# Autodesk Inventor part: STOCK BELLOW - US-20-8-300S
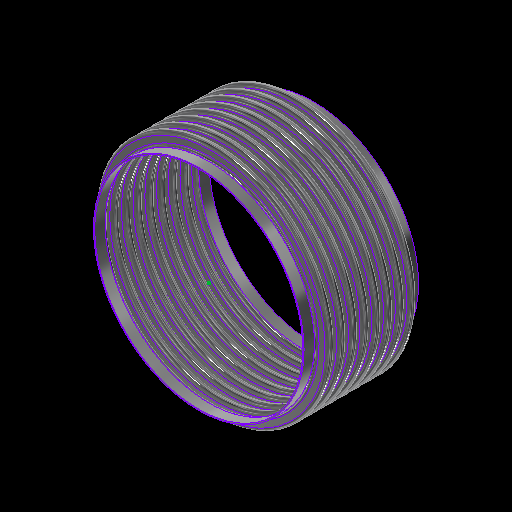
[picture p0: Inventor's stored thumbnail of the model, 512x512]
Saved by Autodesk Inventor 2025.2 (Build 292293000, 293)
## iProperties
Category: 16 GA (0.060 THICK)
RuleStatus: InUse
Created: 2024-01
Part Number: STOCK BELLOW - US-20-8-300S
Project: =STOCK BELLOWS: <Stock Number><SFILL>
Material: ASTM A240-304
Description: =STOCK BELLOWS: <Stock Number>, <SID_> I.D., <SOD_> O.D., <SPLY_> PLY, <Category>, <SNET_CONS> CONS.<PITCH_><STANGENT_> TANGENT<SFILL>
Document SubType Name: Sheet Metal
Designer: GS
Stock Number: U.S-20-8-300S
Surface Area: 21924.1 cm^2
Volume: 3296.49 cm^3
Sheet Metal Rule: Default
Appearance: STAINLESS STEEL
Mass: 26560.8 g
Density: 8.05729 g/cm^3
THK: 0.036
ID: 3.500
OD: 4.250
CONS_: 2
PITCH: 0.500
TANGENT: 0.500
BELLOWS_UPSET: 0.000
d79: 1.000
d82: 1.000
d83: 26.000
d84: 24.000
d174: 8
d214: 8
STHK_: 0.060
SID_: 20.000
SOD_: 22.500
SPITCH_: 1.125
STANGENT__: 1.000
SBELLOWS_UPSET_: 0.000
SDIFF_TAN: 1.000
d252: 2
d275: 2
d287: 0.050
d289: 0.500
d290: 0.000
SOD_NECK: 20 1/4
PLY: 1
PSET: 4.178
PBAR: 1.035
COUNTER: 1.500
NET_TUBE: 3.071
CONS: 2
S_CONS: 0
NET_CONS: 2
ID_M: 88.90 mm
OD_M: 107.95 mm
THK_M: 0.91 mm
ID_U: 3.500 in
OD_U: 4.250 in
THK_U: 0.036 in
TANGENT2: 0.500
TAN_TO_TAN: 1.000 in
d80: 2.571
d81: 10
SID: 2.375
SCONS_: 8
SPITCH: 0.250
STANGENT_: 1.000
SBELLOWS_UPSET: 0.000
SNET_CONS: 8
SS_CONS: 0
SCONS: 8
d190: 8
d191: 1
d192: 1
d193: 8
d194: 0
SIZE: 20.00
PRESSURE: 300
d230: 8
STANGENT: 4.000
SPLY_: 2
d233: 8
d234: 0
d263: 2
d265: 1
d268: 2
d269: 0
d286: 2
d288: 1
d291: 2
d292: 0
SREROLL: 0.750
BLETP: 0.000 ul
PRES_Copy: 85
MATTABLE: 20 GA (0.036 THICK)
PART_NUMBER: U.S-20-8-300S
PITCH_: =, <SPITCH_> PITCH,
CFILL: .
SFILL: .
MESH: ,
COMP: 1.51
EXT: 0.76
LAT: 0.21
ANG: 458
ASR: 11839
LSR: 99004
ANSR: 11664
PRES: 300
COMPM: 15.1
EXTM: 7.55
LATM: 2.10
ASRM: 2073.364
PRESM: 20.684
LSRM: 17338.571
ANSRM: 2042.716
TEMPMIN: 20
TEMPMAX: 800
TEMPMINM: -7
TEMPMAXM: 427
WEIGHTM: 26.561
WEIGHT: 58.556
Author: GS
Keywords: 20 GA (0.036 THICK)
Comments: =STOCK BELLOW - <STOCK NUMBER>
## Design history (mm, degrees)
sketch "Sketch2"
  geometry: L1 (0, -177.245)-(0, 562.856) reference; L2 (45.364, 0)-(44.45, 0); L3 (48.082, -2.718)-(50.343, -2.718); L4 (48.082, -3.632)-(50.343, -3.632); L5 (50.343, -9.982)-(48.082, -9.982); L6 (50.343, -9.068)-(48.082, -9.068); L7 (45.364, -12.7)-(44.45, -12.7); L8 (48.082, 0)-(48.082, -12.7); L9 (50.343, -6.35)-(53.975, -6.35); L10 (44.45, 0)-(44.45, -12.7); L11 (20.376, 102.841)-(20.376, 101.926); L12 (58.262, 457.127)-(58.262, 349.177); L13 (58.262, 444.427)-(58.262, 336.477); L14 (93.133, -58.817)-(93.133, -71.517); L15 (118.746, -66.401)-(118.746, -66.401); L16 (50.343, -9.068)-(50.343, -9.982); L17 (48.082, -9.068)-(48.082, -9.982); L18 (48.082, -9.525)-(50.343, -9.525); L19 (53.975, 0)-(53.975, -12.7); L20 (-50.343, -9.068)-(-50.343, -9.982); L21 (-50.343, -2.718)-(-48.082, -2.718); L22 (-50.343, -3.632)-(-48.082, -3.632); L23 (-48.082, -9.068)-(-50.343, -9.068); L24 (-50.343, -9.525)-(-48.082, -9.525); L25 (-48.082, -9.982)-(-50.343, -9.982); L26 (-48.082, -9.068)-(-48.082, -9.982); L27 (-44.45, 0.653)-(-44.45, -12.047); L28 (-48.082, -6.35)-(-44.45, -6.35); L29 (-50.343, 0.653)-(-50.343, -12.7); L30 (-53.061, 0)-(-53.975, 0); L31 (-53.975, 0)-(-53.975, -12.7); L32 (-53.061, -12.7)-(-53.975, -12.7); A1 r 2.718 centre (48.082, 0) between (45.364, 0) and (48.082, -2.718); A2 r 3.632 centre (48.082, 0) between (44.45, 0) and (48.082, -3.632); A3 r 3.632 centre (50.343, -6.35) between (50.343, -9.982) and (50.343, -2.718); A4 r 2.718 centre (50.343, -6.35) between (50.343, -9.068) and (50.343, -3.632); A5 r 2.718 centre (48.082, -12.7) between (48.082, -9.982) and (45.364, -12.7); A6 r 3.632 centre (48.082, -12.7) between (48.082, -9.068) and (44.45, -12.7); A7 r 3.175 centre (50.343, -6.35) between (50.343, -9.525) and (53.518, -6.35); A8 r 3.175 centre (48.082, -12.7) between (48.082, -9.525) and (44.907, -12.7); A9 r 2.718 centre (-50.343, -12.7) between (-50.343, -9.982) and (-53.061, -12.7); A10 r 2.718 centre (-48.082, -6.35) between (-48.082, -9.068) and (-48.082, -3.632); A11 r 3.175 centre (-48.082, -6.35) between (-48.082, -9.525) and (-44.907, -6.35); A12 r 3.632 centre (-48.082, -6.35) between (-48.082, -9.982) and (-48.082, -2.718); A13 r 3.175 centre (-50.343, -12.7) between (-50.343, -9.525) and (-53.518, -12.7); A14 r 3.632 centre (-50.343, -12.7) between (-50.343, -9.068) and (-53.975, -12.7); A15 r 2.718 centre (-50.343, 0) between (-53.061, 0) and (-50.343, -2.718); A16 r 3.632 centre (-50.343, 0) between (-53.975, 0) and (-50.343, -3.632); 10 further points
  constraints: 62 end point, 38 point on circle, 20 tangent, 16 centre point, 12 parallel, 9 midpoint, 7 vertical, 6 coincident, 6 concentric, 6 point on line, 4 equal radius, 4 perpendicular, 3 horizontal, 1 collinear, 1 horizontal alignment, 10 other
  dimensions: "THK" = 0.9144 distance of L11.start L11.end; "ID" = 88.9 distance of L11.end point (20.376, 13.026); "OD" = 107.95 distance of L12.start L12.end; "PITCH" = 12.7 distance of L12.start L13.start; "TANGENT" = 12.7 distance of L14.start L14.end; "BELLOWS_UPSET" = 0 distance of L15.start L15.end; "d43" = 88.9 diameter of L10 L1 (= ID); "d44" = 107.95 diameter of L9.end L1 (= OD); "d45" = 0.9144 distance between parallel lines of L5 L6 (computed from THK, PLY); "d46" = 3.6322 radius of A3 (computed from PITCH, THK, PLY); "UPSET_PITCH" = 12.7 distance of L2.end L7.end (derived); "SIDEWALL_ANGLE" = 360 deg dimension on L3 L9 (derived); "CON_GAP" = 5.4356 distance of point (48.082, -9.068) point (48.082, -3.632) (derived); "TAN1" = 4.98728 dimension on A8 (derived); "TAN2" = 4.98728 dimension on A7 (derived); "LEG1" = 2.2606 distance of L18.start L18.end (derived); "d278" = 0.9144 distance between parallel lines of L25 L23 (derived); "d279" = 3.6322 radius of A12 (derived); "d280" = 12.7 distance of L30.end L31.end (derived); "d281" = 360 deg dimension on L21 L28 (derived); "d282" = 5.4356 distance of point (-50.343, -9.068) point (-50.343, -3.632) (derived); "d283" = 4.98728 dimension on A13 (derived); "d284" = 4.98728 dimension on A11 (derived); "d285" = 2.2606 distance of L24.start L24.end (derived); "d293" = 88.9 diameter of L27 L1 (derived); "d294" = 107.95 diameter of L31 L1 (derived)
  node "Sketch Rectangular Pattern1" dims "d31" = 25.4, "ID" = 88.9
  node "Sketch Rectangular Pattern2" dims "d39" = 25.4, "PITCH" = 12.7
revolve "CONS" stored, may be unused: angle "d48" = 90 deg
node "BELLOW MIDPLANE"
pattern_linear "Rectangular Pattern2" dims "d52" = 12.7 (= UPSET_PITCH)
sketch "Sketch5"
  geometry: C1 r 45.364 at (0, 0) reference; C2 r 44.45 at (0, 0) reference
extrude "TANGENT" new body sketch "Sketch5" distance "d53" = 12.7 (= TANGENT); taper "d54" = 0 deg
revolve "SAMETAN" stored, may be unused: angle "d65" = 90 deg
revolve "DIFFTAN" stored, may be unused: angle "d70" = 90 deg
sketch "Sketch9"
  geometry: L1 (53.319, 0)-(-53.319, 0) reference; L2 (0, -17.78)-(0, 17.78) reference; L3 (38.085, 0)-(-38.085, 0); L4 (38.085, -11.906)-(38.085, 11.906); L5 (25.385, -11.906)-(25.385, 11.906); L6 (13.15, 11.906)-(13.15, -11.906); L7 (-25.385, -11.906)-(-25.385, 11.906); L8 (-38.085, -11.906)-(-38.085, 11.906); L9 (37.291, -11.906)-(37.291, 11.906); L10 (38.085, -11.906)-(37.291, -11.906); L11 (38.085, 11.906)-(37.291, 11.906); L12 (13.546, 11.906)-(12.753, 11.906); L13 (12.753, 11.906)-(12.753, -11.906); L14 (12.753, -11.906)-(13.546, -11.906); L15 (13.546, -11.906)-(13.546, 11.906); L16 (-13.546, 11.906)-(-13.546, -11.906); L17 (-13.15, 11.906)-(-13.15, -11.906); L18 (-13.546, -11.906)-(-12.753, -11.906); L19 (-12.753, -11.906)-(-12.753, 11.906); L20 (-12.753, 11.906)-(-13.546, 11.906); L21 (-38.085, -11.906)-(-37.291, -11.906); L22 (-37.291, -11.906)-(-37.291, 11.906); L23 (-37.291, 11.906)-(-38.085, 11.906); L24 (-38.085, 11.906)-(-38.085, -11.906); L25 (38.085, -0.397)-(-38.085, -0.397); L26 (-38.085, -0.397)-(-38.085, 0.397); L27 (-38.085, 0.397)-(38.085, 0.397); L28 (38.085, 0.397)-(38.085, -0.397); L29 (-38.085, 11.906)-(38.085, 11.906); L30 (38.085, 11.906)-(38.085, 12.7); L31 (38.085, 12.7)-(-38.085, 12.7); L32 (-38.085, 12.7)-(-38.085, 11.906); L33 (38.085, -11.906)-(-38.085, -11.906); L34 (-38.085, -11.906)-(-38.085, -12.7); L35 (-38.085, -12.7)-(38.085, -12.7); L36 (38.085, -12.7)-(38.085, -11.906); 30 further points
  constraints: 68 end point, 13 midpoint, 13 parallel, 8 horizontal, 7 perpendicular, 6 equal length, 3 point on line, 2 vertical, 14 other
  dimensions: "d115" = 23.8125 distance of L4.start L4.end (derived); "d116" = 12.7 distance between parallel lines of L4 L5 (derived); "d117" = 12.23516 distance between parallel lines of L5 L6 (derived); "d125" = 38.53427 distance between parallel lines of L7 L6 (derived); "d127" = 12.7 distance between parallel lines of L8 L7 (derived); "d128" = 24.93516 distance between parallel lines of L6 L4 (derived); "d130" = 76.16943 distance between parallel lines of L8 L4 (derived); "RULER_THK" = 0.79375 distance between parallel lines of L4 L9; "d135" = 0.79375 distance of L13.end L14.end (derived); "d138" = 26.29911 distance of L13.end L16.end (derived); "d143" = 0.79375 distance of L22.end L8.end (derived); "d144" = 0.79375 distance between parallel lines of L27 L25 (derived)
extrude "RULER" join sketch "Sketch9" distance "d149" = 0.79375 (derived); taper "d150" = 0 deg
extrude "BARS" join sketch "Sketch9" distance "d151" = 0.79375 (derived); taper "d152" = 0 deg
pattern_linear "Rectangular Pattern4" dims "d155" = 26.29911 (derived)
sketch "Sketch13"
  geometry: L1 (93.149, -52.467)-(93.149, -77.867); L2 (257.048, 0)-(254, 0); L3 (257.048, -28.575)-(254, -28.575); L4 (277.082, -22.955)-(262.668, -22.955); L5 (277.082, -19.907)-(262.668, -19.907); L6 (277.082, -14.287)-(285.75, -14.287); L7 (262.668, -5.62)-(277.082, -5.62); L8 (262.668, 0)-(262.668, -28.575); L9 (254, 0)-(254, -28.575); L10 (58.254, 75.069)-(58.254, -496.431); L11 (58.254, 46.494)-(58.254, -525.006); L12 (58.254, -10.656)-(58.254, -582.156); L13 (58.254, -39.231)-(58.254, -610.731); L14 (58.254, -67.806)-(58.254, -639.306); L15 (58.254, -96.381)-(58.254, -667.881); L16 (58.254, -124.956)-(58.254, -696.456); L17 (58.254, 17.919)-(58.254, -553.581); L18 (20.376, 103.45)-(20.376, 101.926); L19 (262.668, -8.668)-(277.082, -8.668); L20 (0, -856.437)-(0, 263.431) reference; L21 (-57.15, 0)-(342.9, 0) reference; A1 r 5.62 centre (262.668, 0) between (257.048, 0) and (262.668, -5.62); A2 r 5.62 centre (262.668, -28.575) between (262.668, -22.955) and (257.048, -28.575); A3 r 8.668 centre (262.668, -28.575) between (262.668, -19.907) and (254, -28.575); A4 r 5.62 centre (277.082, -14.287) between (277.082, -19.907) and (277.082, -8.668); A5 r 8.668 centre (277.082, -14.287) between (277.082, -22.955) and (277.082, -5.62); A6 r 8.668 centre (262.668, 0) between (254, 0) and (262.668, -8.668); 6 further points; 1 other entity
  constraints: 38 end point, 15 point on circle, 9 tangent, 6 centre point, 6 parallel, 5 vertical alignment, 4 point on line, 4 vertical, 3 coincident, 3 concentric, 2 collinear, 2 equal radius, 1 horizontal, 1 perpendicular, 23 other
  dimensions: "SBELLOWS_UPSET_" = 0 distance of point (118.762, -66.401) point (118.762, -66.401); "STOTAL_THK_BELLOW__" = 3.048 distance between parallel lines of L4 L5 (derived); "d224" = 8.66775 radius of A5 (derived); "d225" = 28.575 distance of L2.end L3.end (derived); "SSIDEWALL_ANGLE_" = 360 deg dimension on L7 L6 (derived); "SSCON_GAP_" = 11.2395 distance of point (262.668, -19.907) point (262.668, -8.668) (derived); "d235" = 508 diameter of L9 L20 (derived); "d236" = 571.5 diameter of L6.end L20 (derived)
  node "Sketch Rectangular Pattern4" dims "d228" = 25.4
  node "Sketch Rectangular Pattern5" dims "d229" = 25.4
revolve "SBELLOW" stored, may be unused: angle "d197" = 90 deg
pattern_linear "Rectangular Pattern5" dims "d204" = 28.575 (derived)
revolve "STANGENT" stored, may be unused: angle "d240" = 90 deg
revolve "SSAMETAN" stored, may be unused: angle "d241" = 90 deg
revolve "SDIFFTAN" stored, may be unused: angle "d246" = 90 deg
revolve "INVCON" stored, may be unused: angle "d295" = 90 deg
pattern_linear "Rectangular Pattern6" dims "d298" = 12.7 (derived)
revolve "INVTANGENT" stored, may be unused: angle "d302" = 90 deg
revolve "INVSAMETAN" stored, may be unused: angle "d307" = 90 deg
revolve "INVDIFFTAN" stored, may be unused: angle "d312" = 90 deg
sketch "ID BELLOW MOUNT CALC"
  geometry: L1 (44.45, 0)-(38.1, 0); L2 (38.1, 0)-(38.1, 12.7); L3 (38.1, 12.7)-(44.45, 12.7); L4 (44.45, 12.7)-(44.45, 0); L5 (36.513, 12.7)-(35.598, 12.7); L6 (35.598, 12.7)-(35.598, 0); L7 (35.598, 0)-(36.513, 0); L8 (36.513, 0)-(36.513, 12.7); L9 (0, -2.54)-(0, 15.24) reference; L10 (-8.89, 0)-(53.34, 0) reference; 1 further point
  constraints: 16 end point, 5 parallel, 2 collinear, 2 horizontal, 2 perpendicular
  dimensions: "d314" = 12.7 distance of L5.end L6.end (derived); "d315" = 0.9144 distance of L5.start L5.end (derived); "IG" = 1.5875 distance between parallel lines of L2 L8; "PIPE_OD" = 88.9 diameter of L4 L9; "PIPE_WALL" = 6.35 distance of L2.end L3.end; "ID_MT_BELLOW" = 71.1962 diameter of L6 L9 (derived)
revolve "CFILL" stored, may be unused: angle "d320" = 90 deg
pattern_linear "Rectangular Pattern7" dims "d323" = 12.7 (derived)
revolve "SFILL" stored, may be unused: angle "d324" = 90 deg
pattern_linear "Rectangular Pattern8" dims "d327" = 28.575 (derived)
node "STOCK BELLOW MIDPLANE"
node "BELLOW"
sketch "Sketch6"
  geometry: L1 (-12.7, 45.364)-(0, 45.364); L2 (0, 45.364)-(0, 44.45); L3 (0, 44.45)-(-12.7, 44.45); L4 (-12.7, 44.45)-(-12.7, 45.364); L5 (10.16, 0)-(-60.96, 0) reference; L6 (-38.1, -89.422)-(-38.1, 153.44) reference; 1 further point
  constraints: 8 end point, 2 parallel, 1 horizontal, 1 perpendicular
  dimensions: "d61" = 12.7 distance of L2.end L3.end (derived); "d62" = 0.9144 distance of L1.end L2.end (derived); "d63" = 88.9 diameter of L3 L5 (derived); "d64" = 25.4 distance between parallel lines of L4 L6 (derived)
sketch "Sketch12"
  geometry: 1 further point
sketch "Sketch14"
  geometry: L1 (-25.4, 257.048)-(0, 257.048); L2 (0, 257.048)-(0, 254); L3 (0, 254)-(-25.4, 254); L4 (-25.4, 254)-(-25.4, 257.048); L5 (5.08, 0)-(-30.48, 0) reference; L6 (0, -51.41)-(0, 308.458) reference; 1 further point
  constraints: 8 end point, 2 parallel, 1 collinear, 1 horizontal, 1 perpendicular
  dimensions: "d237" = 3.048 distance of L3.end L1.start (derived); "d238" = 508 diameter of L3 L5 (derived); "d239" = 25.4 distance of L1.start L1.end (derived); "SOD_NECK" = 514.096 diameter of L1 L5 (derived)
sketch "Sketch15"
  geometry: L1 (-51.41, 0)-(308.458, 0) reference; L2 (254, -228.6)-(257.048, -228.6); L3 (257.048, -228.6)-(257.048, -254); L4 (257.048, -254)-(254, -254); L5 (254, -254)-(254, -228.6); L6 (0, -307.34)-(0, 66.04) reference; 1 further point
  constraints: 8 end point, 2 parallel, 1 horizontal, 1 perpendicular
  dimensions: "d205" = 25.4 distance of L4.end L2.start (derived); "d206" = 3.048 distance of L3.end L4.end (derived); "d207" = 508 diameter of L5 L6 (derived); "d208" = 228.6 distance between parallel lines of L1 L2 (derived)
node "TANGENT_"
node "SAME_TAN"
sketch "Sketch8"
  geometry: L1 (45.364, -25.4)-(44.45, -25.4); L2 (44.45, -25.4)-(44.45, -38.1); L3 (44.45, -38.1)-(45.364, -38.1); L4 (45.364, -38.1)-(45.364, -25.4); L5 (0, -48.26)-(0, 22.86) reference; L6 (-89.422, 0)-(153.44, 0) reference; 1 further point
  constraints: 8 end point, 2 parallel, 1 horizontal, 1 perpendicular
  dimensions: "d66" = 88.9 diameter of L2 L5 (derived); "TOTAL_THK_BELLOW" = 0.9144 distance of L2.end L3.end (derived); "d68" = 25.4 distance between parallel lines of L1 L6 (derived); "d69" = 12.7 distance of L1.end L2.end (derived)
node "DIFF_TAN"
node "Sketch Rectangular Pattern3" dims "d138" = 26.29911 (derived), "d141" = 25.4
node "SBELLOW_"
node "STANGENT_"
node "SSAME_TAN"
sketch "Sketch16"
  geometry: L1 (257.048, -228.6)-(254, -228.6); L2 (254, -228.6)-(254, -254); L3 (254, -254)-(257.048, -254); L4 (257.048, -254)-(257.048, -228.6); L5 (0, -307.34)-(0, 66.04) reference; L6 (-51.41, 0)-(308.458, 0) reference; 1 further point
  constraints: 8 end point, 2 parallel, 1 horizontal, 1 perpendicular
  dimensions: "SDIFF_TAN" = 25.4 distance of L3.end L1.start; "d243" = 3.048 distance of L2.end L3.end (derived); "d244" = 228.6 distance between parallel lines of L1 L6 (derived); "d245" = 508 diameter of L2 L5 (derived)
node "SDIFF_TAN"
body "Solid15"
sketch "Sketch17"
  geometry: L1 (53.975, 12.7)-(53.061, 12.7); L2 (53.061, 12.7)-(53.061, 0); L3 (53.061, 0)-(53.975, 0); L4 (53.975, 0)-(53.975, 12.7); L5 (0, -2.54)-(0, 15.24) reference; L6 (-10.795, 0)-(64.77, 0) reference; 2 further points
  constraints: 8 end point, 2 parallel, 1 horizontal, 1 midpoint, 1 perpendicular, 1 point on line
  dimensions: "INVTANGENT" = 12.7 distance of L3.end L1.start (derived); "d300" = 0.9144 distance of L1.start L1.end (derived); "d301" = 107.95 diameter of L4 L5 (derived)
body "Solid16"
sketch "Sketch18"
  geometry: L1 (53.975, -25.4)-(53.061, -25.4); L2 (53.061, -25.4)-(53.061, -38.1); L3 (53.061, -38.1)-(53.975, -38.1); L4 (53.975, -38.1)-(53.975, -25.4); L5 (-10.795, 0)-(64.77, 0) reference; L6 (0, -48.26)-(0, 22.86) reference; 1 further point
  constraints: 8 end point, 2 parallel, 1 horizontal, 1 perpendicular
  dimensions: "d303" = 25.4 distance between parallel lines of L1 L5 (derived); "d304" = 12.7 distance of L3.end L1.start (derived); "d305" = 0.9144 distance of L2.end L3.end (derived); "d306" = 107.95 diameter of L4 L6 (derived)
body "Solid17"
sketch "Sketch19"
  geometry: L1 (53.975, -25.4)-(53.061, -25.4); L2 (53.061, -25.4)-(53.061, -38.1); L3 (53.061, -38.1)-(53.975, -38.1); L4 (53.975, -38.1)-(53.975, -25.4); L5 (0, -48.26)-(0, 22.86) reference; L6 (-10.795, 0)-(64.77, 0) reference; 1 further point
  constraints: 8 end point, 2 parallel, 1 horizontal, 1 perpendicular
  dimensions: "d308" = 12.7 distance of L1.end L2.end (derived); "d309" = 107.95 diameter of L4 L5 (derived); "d310" = 0.9144 distance of L2.end L3.end (derived); "d311" = 25.4 distance between parallel lines of L1 L6 (derived)
body "Solid18"
body "Solid19"
body "Solid20"
other parameters: "BMPL" = -114.3, "PSET" = 106.1212 (computed from OD, THK, PLY) [user parameter], "PBAR" = 26.29911 (= 0.570796 x PITCH + OD - ID) [user parameter; used in 1 equation term], "COUNTER" = 15 [user parameter], "NET_TUBE" = 77.99823 (computed from CONS_, PBAR, TANGENT) [user parameter], "S_CONS" = 0 [user parameter; used in 1 equation term], "ID_M" = 88.9 (= ID) [user parameter], "OD_M" = 107.95 (= OD) [user parameter], "THK_M" = 0.9144 (= THK) [user parameter], "ID_U" = 88.9 (= ID) [user parameter], "OD_U" = 107.95 (= OD) [user parameter], "THK_U" = 0.9144 (= THK) [user parameter], "D_UNITS" = 0 [user parameter], "TANGENT2" = 12.7 [user parameter], "TAN_TO_TAN" = 25.4 [user parameter], "OD_NECK" = 90.7288 [user parameter], "d79" = 25.4, "d80" = 65.29823 [user parameter], "d82" = 25.4, "d83" = 660.4, "d84" = 609.6, "sa_0" = 4, "FRAME_THK" = 0.79375 [user parameter], "CON_FLAT" = 12.23516 [user parameter], "SID" = 60.325 [user parameter], "SPITCH" = 6.35 [user parameter], "STANGENT_" = 25.4 [user parameter], "SBELLOWS_UPSET" = 0 [user parameter], "SS_CONS" = 0 [user parameter], "STAN_TO_TAN_" = 228.6 [user parameter], "d100" = 3.048 [user parameter], "d191" = 25.4 [user parameter], "d194" = 0 [user parameter], "STANGENT" = 101.6 [user parameter], "d234" = 0 [user parameter], "SUPSET_PITCH_" = 28.575 [user parameter], "d269" = 0 [user parameter], "d287" = 1.27, "d289" = 12.7, "d290" = 0, "d292" = 0 [user parameter], "Thickness" = 3.048 (derived), "KFactor" = 4.4, "BendRadius" = 3.048 (derived), "BendReliefWidth" = 3.048 (derived), "BendReliefDepth" = 1.524 (derived), "CornerReliefSize" = 12.192 (derived), "SeamGap" = 0.00508, "MinimumRemnant" = 6.096 (derived), "TransitionRadius" = 3.048 (derived), "JacobiRadiusSize" = 3.048 (derived), "GapSize" = 3.048 (derived), "SREROLL" = 19.05 [user parameter], "CUR_STK_PITCH" = 28.575 [user parameter], "d328" = -114.3 (derived), "ASR" = 118390 [user parameter], "LSR" = 990040 [user parameter], "ANSR" = 116640 [user parameter], "BLETP" = 0 [user parameter], "ASRM" = 20733.6407 [user parameter], "PRESM" = 206.83949 [user parameter], "LSRM" = 173385.7052 [user parameter], "ANSRM" = 20427.1632 [user parameter], "TEMPMIN" = 2664.83333 [user parameter], "TEMPMAX" = 6998.16667 [user parameter], "TEMPMINM" = 2664.83333 [user parameter], "TEMPMAXM" = 6998.16667 [user parameter], "WEIGHT" = 265.6078 [user parameter], "WEIGHTM" = 0.26561 [user parameter]
